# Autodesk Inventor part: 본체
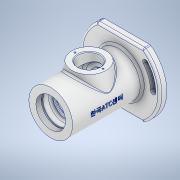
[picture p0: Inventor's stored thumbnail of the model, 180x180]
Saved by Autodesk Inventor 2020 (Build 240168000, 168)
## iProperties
Created: 2022-05
Part Number: 본체
Material: 알루미늄 6061
Document SubType Name: Modeling
Designer: Student
Mass: 693.292 g
Surface Area: 620.445 cm^2
Volume: 256.775 cm^3
Density: 2.7 g/cm^3
Appearance: 알루미늄 - 평지
Author: Student
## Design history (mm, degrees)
sketch "스케치1"
  geometry: L1 (0, 65.727)-(0, -65.727); L2 (15, -44.3)-(15, -37.7); L3 (15, -37.7)-(11, -37.7); L4 (11, -37.7)-(11, -35); L5 (11, -35)-(15, -35); L6 (15, -35)-(15, -30); L7 (15, -30)-(17.5, -30); L8 (17.5, -30)-(17.5, -19); L9 (17.5, -19)-(27, -19); L10 (27, -19)-(27, 19); L11 (27, 19)-(17.5, 19); L12 (17.5, 19)-(17.5, 30); L13 (17.5, 30)-(18.5, 30); L14 (18.5, 30)-(18.5, 31.75); L15 (18.5, 31.75)-(17.5, 31.75); L16 (17.5, 31.75)-(17.5, 33); L17 (18.5, 34)-(22.5, 34); L18 (24, 48)-(24, 45); L19 (24, 45)-(22.5, 45); L20 (22.5, 45)-(22.5, 34); L21 (24, 48)-(22.972, 48); L22 (32, 56)-(0, 56); L23 (0, 48)-(22.972, 48); L24 (0, 56)-(0, 48); L25 (32, 56)-(32, -46); L26 (32, -46)-(36, -46); L27 (36, -46)-(36, -59); L28 (36, -59)-(30, -59); L29 (15.404, -45)-(20, -45); L30 (20, -45)-(30, -59); L31 (17.5, 33)-(18.5, 34); L32 (15, -44.3)-(15.404, -45); 4 further points
  constraints: 64 end point, 19 perpendicular, 8 point on line, 3 horizontal, 2 vertical, 1 coincident, 1 collinear, 1 midpoint, 1 parallel
  dimensions: "d0" = 45 diameter of L20 L1; "d1" = 48 diameter of L18 L1; "d3" = 54 diameter of L10 L1; "d5" = 64 diameter of L25 L1; "d6" = 30 diameter of L6 L1; "d7" = 22 diameter of L4 L1; "d8" = 35 diameter of L8 L1; "d9" = 30 diameter of L2 L1; "d10" = 35 diameter of L12 L1; "d11" = 37 diameter of L14 L1; "d12" = 102 distance of L22.start L25.end; "d13" = 7.3 distance of point (15, -45) L2.end; "d14" = 72 diameter of L27 L1; "d15" = 60 diameter of L28.end L1; "d16" = 14 distance between parallel lines of L28 L29; "d17" = 13 distance between parallel lines of L28 L26; "d18" = 5 distance of L5.end L6.end; "d19" = 11 distance of L7.end L8.end; "d22" = 11 distance of L11.end L12.end; "d23" = 1.75 distance of L13.end L14.end; "d24" = 4 distance between parallel lines of L13 L17; "d25" = 22 distance between parallel lines of L17 L22; "d26" = 8 distance between parallel lines of L23 L22; "d27" = 3 distance of L18.start L18.end; "d28" = 29 distance between parallel lines of L28 L7; "d29" = 40 diameter of L29.end L1; "d31" = 1 distance of L16.end point (17.5, 34); "d32" = 1 distance of L17.start point (17.5, 34) (= d31); "d33" = 0.7 distance of L2.start point (15, -45); "d34" = 30 deg angle of L2 L32; "d53" = 56 distance from line of point (0, 0) L22
revolve "회전1" sketch "스케치1" stored, may be unused: angle "d35" = 90 deg
sketch "스케치2"
  geometry: C1 r 32 at (0, 0) reference; 1 further point
hole "구멍1" sketch "스케치2" at (0, 0) diameter "d36" = 43.376; stored, may be unused: countersink angle "d40" = 90 deg, drill point angle "d42" = 0 deg; dims "d37" = 8, "d38" = 4, "d39" = 2, "d41" = 8
fillet "모깎기1" dims "d43" = 3
chamfer "모따기1" distance "d44" = 1; stored, may be unused: second distance "d45" = 2, angle "d46" = 45 deg
fillet "모깎기2" dims "d47" = 3
fillet "모깎기3" dims "d48" = 0.5
fillet "모깎기4" dims "d49" = 0.6
chamfer "모따기2" distance "d50" = 1; stored, may be unused: second distance "d51" = 2, angle "d52" = 45 deg
node "작업 평면1"
sketch "스케치3"
  geometry: C1 r 25 at (0, 0); 1 further point
  constraints: 1 centre point, 1 coincident
  dimensions: "d55" = 50 diameter of C1
extrude "돌출1" join sketch "스케치3" stored distance "d56" = 10; taper "d57" = 10 deg
sketch "스케치4"
  geometry: C1 r 16 at (0, 0); 1 further point
  constraints: 1 centre point, 1 coincident
  dimensions: "d58" = 32 diameter of C1
extrude "돌출2" cut sketch "스케치4" distance "d59" = 20; taper "d60" = 0 deg
chamfer "모따기3" distance "d61" = 1; stored, may be unused: second distance "d62" = 2, angle "d63" = 45 deg
sketch "스케치5" dims "d64" = 41
  geometry: 3 further points
  constraints: 2 horizontal alignment, 1 coincident, 2 other
hole "구멍2" sketch "스케치5" at (-20.5, 0) diameter "d65" = 2.459; stored, may be unused: countersink angle "d69" = 90 deg, drill point angle "d71" = 118 deg; dims "d66" = 6, "d67" = 4, "d68" = 2, "d70" = 8
node "작업 평면2"
chamfer "모따기4" distance "d81" = 1; stored, may be unused: second distance "d82" = 2, angle "d83" = 45 deg
sketch "스케치7"
  geometry: L1 (-33.985, 47)-(33.985, 47); L2 (-33.985, -47)-(33.985, -47); C1 r 32 at (0, 0) reference; A1 r 58 centre (0, 0) between (-33.985, 47) and (-33.985, -47); A2 r 58 centre (0, 0) between (33.985, -47) and (33.985, 47); 1 further point
  constraints: 4 end point, 4 point on circle, 2 centre point, 2 horizontal, 1 coincident
  dimensions: "d84" = 58 radius of A1; "d85" = 47 distance from line of L1 point (0, 0); "d86" = 94 distance between parallel lines of L2 L1; "d87" = 58 radius of A2
extrude "돌출4" join sketch "스케치7" distance "d88" = 10; taper "d89" = 0 deg
fillet "모깎기7" dims "d90" = 3
fillet "모깎기8" dims "d91" = 3
fillet "모깎기9" dims "d92" = 3
sketch "스케치8" dims "d96" = 96
  geometry: L1 (-93.009, 0)-(93.009, 0); L2 (-57.242, 48.031)-(57.242, -48.031); C1 r 11 at (0, 0) reference; C2 r 4 at (-36.77, 30.854); A1 r 48 centre (0, 0) between (-36.77, 30.854) and (-48, 0); A2 r 50.25 centre (0, 0) between (-38.494, 32.3) and (-50.25, 0); A3 r 45.75 centre (0, 0) between (-35.047, 29.408) and (-45.75, 0); A4 r 2.25 centre (-36.77, 30.854) between (-35.047, 29.408) and (-38.494, 32.3); A5 r 2.25 centre (-48, 0) between (-50.25, 0) and (-45.75, 0); 5 further points
  constraints: 10 point on circle, 6 centre point, 4 coincident, 4 end point, 4 tangent, 2 midpoint, 1 horizontal, 1 point on line, 3 other
  dimensions: "d98" = 40 deg angle of L2 L1; "d99" = 4.5 diameter of A5; "d100" = 8 diameter of C2; "d101" = 59.78472 distance from line of L1.end L2; "d102" = 48.03136 distance from line of L2.end L1; "d103" = 29.40753 distance from line of A3.end L2
extrude "돌출5" cut sketch "스케치8" distance "d104" = 10; taper "d105" = 0 deg
sketch "스케치9"
  geometry: C1 r 20.897 at (33, -44) reference; A1 r 4 centre (69.77, -13.146) between (73.58, -14.364) and (70.033, -17.138) reference; A2 r 2.25 centre (81, -44) between (78.75, -44) and (83.25, -44) reference; A3 r 48 centre (33, -44) between (81, -44) and (69.77, -13.146); A4 r 52 centre (33, -44) between (85, -44) and (72.834, -10.575); A5 r 44 centre (33, -44) between (77, -44) and (66.706, -15.717); A6 r 4 centre (81, -44) between (77, -44) and (85, -44); A7 r 4 centre (69.77, -13.146) between (72.834, -10.575) and (66.706, -15.717); 3 further points
  constraints: 10 point on circle, 5 centre point, 4 tangent, 1 coincident
  dimensions: "d106" = 8 diameter of A6
extrude "돌출6" cut sketch "스케치9" distance "d107" = 4.4; taper "d108" = 0 deg
node "작업 평면3"
sketch "스케치10"
  geometry: L1 (-46.4, -56)-(46.4, -56) reference; 2 further points
  constraints: 1 vertical alignment, 1 other
  dimensions: "d113" = 62 distance from line of L1 point (0, 6)
feature "엠보싱1" sketch "스케치10" dims "d6" = 30, "d114" = 0.5, "d115" = 0
fillet "모깎기10" dims "d116" = 3
node "솔리드1"
pattern_circular "원형 패턴1" dims angle "d94" = 360 deg
pattern_circular "원형 패턴2" dims angle "d110" = 360 deg
node "투영된 루프1"
other parameters: "d54" = 38, "d72" = -13, "d112" = 33
